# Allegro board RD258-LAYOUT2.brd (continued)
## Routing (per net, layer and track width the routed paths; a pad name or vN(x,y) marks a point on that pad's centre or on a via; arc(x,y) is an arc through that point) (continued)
SIG00089: length 1.9
  BOTTOM w0.15: R70.1 62.45,45.75 62.45,46.88 62.42,46.9 Q10.1
SIG00090: length 4.9
  BOTTOM w0.15: Q10.3 63.58,47.9 63.83,48.15 R67.1 65.25,48.8 C78.2 66.25,48.8 66.3,48.85 IC23.1
SIG00092: length 3.3
  BOTTOM w0.2: IC27.1 70.4,49.15 70.1,48.85 IC23.6
SIG00094: length 4.5
  BOTTOM w0.15: IC22.1 72,52.8 72.1,52.9 72.1,53.85 71.95,54 71.4,54 70.85,53.45 70.1,53.45 69.9,53.65 IC27.7
SIG00096: length 1.2
  BOTTOM w0.15: R72.1 72.53,54.62 IC22.4
SIG00097: length 5
  BOTTOM w0.3: R74.2 75.2,53.25 Q9.1 ; R74.2 R72.2 ; R74.2 TP39.1
SIG00098: length 1.2
  BOTTOM w0.15: IC26.6 73.4,38.75 Q8.1
SIG00099: length 4.7
  BOTTOM w0.15: IC31.3 20.8,32.15 20.9,32.25 20.9,32.95 R79.2 20.45,34.25 21,34.8 C87.2
SIG00100: length 3.4
  BOTTOM w0.2: R79.1 21.3,32.75 21.3,31.2 21.65,30.85 IC31.6
SIG00101: length 3.1
  BOTTOM w0.2: IC32.1 23.7,31.05 22.6,32.15 IC31.4
SIG00103: length 3.1
  BOTTOM w0.15: IC32.6 23.7,27.2 22.9,26.4 22.55,26.4 Q12.1
SIG00104: length 6.2
  BOTTOM w0.15: Q12.3 D25.1 20.7,21.25 R75.1 22.18,21 Q11.1
SIG00106: length 16.4
  BOTTOM w0.15: IC30.3 24.9,35.35 R83.2 25,34 C86.2 27.1,31.6 27.1,26.75 24.7,24.35 R78.1
SIG00107: length 2.6
  BOTTOM w0.15: IC30.1 R81.2 R76.1
SIG00108: length 11.4
  BOTTOM w0.15: R80.2 25.15,40.65 25.35,40.45 25.35,39.05 24.9,38.6 IC30.4
SIG00109: length 2.1
  BOTTOM w0.15: R80.1 16.25,37.08 Q14.1
SIG00110: length 6.4
  BOTTOM w0.15: Q14.3 14.4,35.98 14.4,34.2 R77.1 14.8,33.8 C88.2 15.1,32.15 IC28.1
SIG00112: length 2.5
  BOTTOM w0.15: IC28.6 17.43,32.15 16.88,31.6 16.7,31.6 16.6,31.5 IC33.1
SIG00114: length 3
  BOTTOM w0.15: IC29.1 IC33.7
SIG00115: length 1.2
  BOTTOM w0.15: R82.1 IC29.4
SIG00117: length 7.2
  TOP w0.3: v1(14.4,23.2) 14.4,24.45 TP40.1
  BOTTOM w0.3: v1(14.4,23.2) R82.2 R84.2 16.3,21.3 Q13.1
SIG00118: length 14.2
  TOP w0.15: v2(56.5,49.1) 54.8,49.1 53.85,48.15 53.85,45.77 54.35,45.27 59.88,45.27 v2(60.35,44.8)
  BOTTOM w0.15: v2(56.5,49.1) 56.35,48.68 IC36.4 ; IC34.6 v2(60.35,44.8)
SIG00119: length 15.4
  TOP w0.15: v2(55.2,44.7) 59.3,44.7 v2(60.35,43.65)
  BOTTOM w0.15: R98.1 61,44.3 v2(60.35,43.65) ; 55.35,46.95 IC36.6 ; 55.35,46.95 55.2,46.95 ; 55.35,46.95 55.2,46.8 ; 55.35,46.95 55.2,47.1 ; IC34.2 55.6,44.3 v2(55.2,44.7) 55.2,46.8 ; 55.2,46.8 55.2,46.95 ; 55.2,47.1 55.2,46.95 ; 55.2,47.1 55.2,48 54.95,48.25 IC36.3
SIG00120: length 3.5
  BOTTOM w0.15: IC37.1 59.7,48.65 C99.2 61,48.85 R98.2
SIG00121: length 10.6
  TOP w0.15: v2(59,46.1) 58.48,45.58 54.98,45.58 v2(54.45,46.1)
  BOTTOM w0.15: IC34.1 55.25,43.8 54.45,44.6 v2(54.45,46.1) ; v2(59,46.1) 58.15,46.95 IC37.4
SIG00122: length 9.3
  TOP w0.15: IC35.7 62.25,47.15 61.9,46.8 60.6,46.8 TP30.1 60.08,46.92 56.77,46.92 v2(55.95,46.1)
  BOTTOM w0.15: IC34.3 56.2,44.8 55.95,45.05 v2(55.95,46.1)
SIG00123: length 11
  TOP w0.15: v2(57.05,46.1) 57.58,46.62 59.27,46.62 60.15,45.75 61.6,45.75 TP32.1 62.75,46.9 IC35.8
  BOTTOM w0.15: v2(57.05,46.1) 57.9,46.1 58.5,45.5 58.5,44.6 58.8,44.3 IC34.7
SIG00124: length 4.7
  BOTTOM w0.15: IC37.6 58.25,48.25 58.5,48 58.5,47.4 58.95,46.95 IC37.3 59.7,45.44 59.56,45.3 IC34.5
SIG00126: length 8.2
  TOP w0.2: R90.1 67.8,52.35 63.55,52.35 62.25,51.05 IC35.4
SIG00127: length 4.2
  TOP w0.15: v2(64.5,51.65) 63.45,51.65 62.75,50.95 IC35.3
  BOTTOM w0.15: C94.2 63.42,51.15 63.92,51.65 v2(64.5,51.65)
SIG00129: length 7.8
  TOP w0.2: R103.1 68.8,48.45 67,46.65 64.4,46.65 63.75,47.3 IC35.10
SIG00130: length 1.7
  TOP w0.2: R103.2 71.7,49.85 Q16.3
SIG00132: length 4.1
  TOP w0.2: R90.2 73.65,51.35 73.8,51.5 Q15.3
SIG00134: length 1.2
  BOTTOM w0.15: Q17.3 R104.2
SIG00137: length 2.8
  TOP w0.5: R85.2 R86.1
SIG00138: length 3.2
  TOP w0.5: R86.2 D26.1
SIG00139: length 2.4
  TOP w1: D26.2 77.55,21.7 D27.1
SIG00140: length 2.4
  TOP w1: D28.1 82.35,22.7 D27.2
SIG00141: length 2.4
  TOP w1: D29.1 87.15,23.7 D28.2
SIG00142: length 13.3
  TOP w0.15: v2(38.7,23.35) 37.88,24.18 33.38,24.18 33.1,23.9 IC40.6 32.05,23.9 31.6,23.45 31.6,22.75 31.45,22.6 IC40.3 30.35,22.6 30.15,22.4 v2(30.15,21.8)
  BOTTOM w0.15: R119.1 v2(30.15,21.8) ; IC38.2 v2(38.7,23.35)
SIG00143: length 10.1
  TOP w0.15: v2(38.7,24.35) 39.4,23.65 39.4,23.1 39.05,22.75 38.2,22.75 37.35,23.6 v2(34,23.6)
  BOTTOM w0.15: v2(34,23.6) 33.7,23.9 IC41.4 ; v2(38.7,24.35) 38.2,23.85 IC38.1
SIG00144: length 6.3
  TOP w0.15: IC39.7 35.75,19.6 36.25,20.1 TP35.1 37.47,20.57 v2(37.85,20.8)
  BOTTOM w0.15: IC38.3 38.1,22.85 38.35,22.6 38.35,21.3 v2(37.85,20.8)
SIG00145: length 3.9
  BOTTOM w0.15: IC41.1 29.25,22.6 R119.2 C111.2
SIG00146: length 6.1
  TOP w0.15: IC39.8 35.25,19.3 34.8,19.75 TP37.1 35.1,20.1 v2(35.8,20.8)
  BOTTOM w0.15: IC38.7 35.5,23.35 35.8,23.05 v2(35.8,20.8)
SIG00147: length 2.3
  TOP w0.15: v2(34,22.6) IC40.4
  BOTTOM w0.15: IC38.6 34.25,22.85 v2(34,22.6)
SIG00148: length 5.3
  BOTTOM w0.15: IC41.3 31.35,23.9 31.6,23.65 31.6,23.1 32.1,22.6 IC41.6 33.2,22.6 33.75,22.05 34.45,22.05 34.75,22.35 IC38.5
SIG00150: length 8.5
  TOP w0.2: R110.1 29.2,14.3 29.55,13.95 34.45,13.95 35.75,15.25 IC39.4
SIG00151: length 4.6
  TOP w0.15: v2(33.05,14.5) 34.4,14.5 35.25,15.35 IC39.3
  BOTTOM w0.15: C106.2 32.17,13.62 v2(33.05,14.5)
SIG00153: length 4
  TOP w0.2: Q18.3 24.2,14.75 24.4,14.95 R110.2
SIG00155: length 7.6
  TOP w0.2: R123.1 29.2,17.75 31.1,19.65 33.5,19.65 34.25,18.9 IC39.10
SIG00156: length 1.7
  TOP w0.2: Q19.3 26.3,16.45 R123.2
SIG00158: length 1.4
  BOTTOM w0.15: Q20.3 R124.2
SIG00161: length 2.8
  TOP w0.5: R106.1 R105.2
SIG00162: length 3.6
  TOP w0.5: R106.2 28.55,63.5 D34.1
SIG00163: length 2.2
  TOP w1: D35.1 D34.2
SIG00164: length 2.2
  TOP w1: D36.1 D35.2
SIG00165: length 2.2
  TOP w1: D37.1 D36.2
SIG00167: length 11.2
  BOTTOM w0.15: R178.2 R128.1 57.95,15.82 58.17,15.6 63.7,15.6 66.08,13.22 Q22.1
SIG00168: length 2.4
  BOTTOM w0.15: R133.2 R131.1
SIG00169: length 1.7
  BOTTOM w0.15: R136.1 57.2,19.25 Q24.1
SIG00170: length 10.1
  TOP w0.15: R129.1 58.73,13.25 C120.2 58.88,13.25 R132.2 61,12.4 64.4,12.4 v2(64.85,11.95)
  BOTTOM w0.15: IC51.3 65.08,11.35 65.06,11.39 v2(64.85,11.95)
SIG00171: length 3
  BOTTOM w0.15: 70.45,4.28 R126.1 R179.2
SIG00173: length 3.1
  BOTTOM w0.15: Q23.3 68.47,5.42 R135.2 68.3,5.35 67.95,5 D42.2
SIG00174: length 2.4
  BOTTOM w0.15: Q25.1 71.2,8.7 R138.1
SIG00175: length 6.2
  BOTTOM w0.15: IC51.6 65.08,5.38 D42.1 64.85,4.4 R127.1 63.58,2.75
SIG00176: length 12.6
  TOP w0.15: v2(70.15,11.6) 68.8,10.25 64.45,10.25 v2(63.65,11.05)
  BOTTOM w0.15: v2(63.65,11.05) 63.77,10.46 IC51.1 ; R137.1 C128.2 70.15,10.7 v2(70.15,11.6) 70.75,12.2 IC48.1
SIG00177: length 2.8
  TOP w0.15: R143.2 64.85,5.75 v2(64.42,5.9)
  BOTTOM w0.15: IC51.7 v2(64.42,5.9)
SIG00178: length 19.6
  TOP w0.15: R143.1 R139.1 69.65,4.7 C129.2 71.6,4.7 73.35,6.45 73.35,8.9 71.4,10.85 71.4,11.9 70.55,12.75 v2(70.15,12.95)
  BOTTOM w0.15: v2(70.15,12.95) 70.3,13.25 70.3,14.5 71.4,15.6 IC42.1
SIG00179: length 1.3
  TOP w0.3: R142.2 R140.1
SIG00180: length 4.3
  TOP w0.3: 58.13,7.78 56.62,7.78 R147.2 55.23,7.85 C131.2 55.05,7.72 R142.1
SIG00181: length 6.2
  TOP w0.3: 62.47,7.78 61.12,7.78 60.48,7.12 IC50.4 58.13,5.98 R146.2
SIG00182: length 3.7
  TOP w0.3: R146.1 60.3,5.7 R149.2 61.73,7.12 IC50.5
SIG00183: length 14.7
  TOP w0.15: TP46.1 72.7,12.15 v2(74.6,14.05)
  BOTTOM w0.15: IC49.5 71.25,22.05 74.8,18.5 74.8,14.45 v2(74.6,14.05) 74.05,13.5 IC48.4
SIG00184: length 1.5
  TOP w0.15: R144.2 63.52,9.07 IC50.8
SIG00185: length 15.6
  TOP w0.15: v2(67.2,14.25) 67.95,13.5 68.7,13.5 69.95,12.25 70.35,12.25 70.8,11.8 70.8,9.65 C132.2 R144.1
  BOTTOM w0.15: IC45.1 67.6,14.65 v2(67.2,14.25)
SIG00186: length 14.9
  BOTTOM w0.15: IC53.1 62,31 62.1,31.1 62.1,32.3 61.85,32.55 60.3,32.55 58.9,31.15 58.9,24.4 58.2,23.7 57.45,23.7 57.15,24 IC47.3
SIG00190: length 25.8
  TOP w0.15: v2(70.88,21.12) 70.88,23.57 v2(71.2,23.9)
  BOTTOM w0.15: v2(70.88,21.12) 70.88,19.88 71.4,19.35 IC42.6 71.4,18.15 70.9,17.65 70.35,17.65 70.1,17.4 IC42.3 ; R138.2 73.35,10.65 75.4,12.7 75.4,19.7 v2(71.2,23.9)
SIG00191: length 12.3
  TOP w0.15: v2(66.9,25.9) v2(64.85,25.9)
  BOTTOM w0.15: IC46.1 v2(64.85,25.9) ; IC42.4 69.85,18.8 69.17,19.48 69.17,20.16 68.8,20.53 68.42,20.53 67.3,21.65 67.3,25.5 v2(66.9,25.9)
SIG00192: length 2.9
  BOTTOM w0.15: IC45.3 66.3,17.55 66.4,17.65 67.15,17.65 67.6,18.1 IC45.6
SIG00193: length 2.8
  BOTTOM w0.15: IC48.6 72.75,12.2 72.3,12.65 72.3,13.3 72.1,13.5 IC48.3
SIG00194: length 19.3
  TOP w0.15: v2(65.4,28) v2(66.9,28)
  BOTTOM w0.15: IC45.4 66.3,19.95 66.9,20.55 66.9,25 66.35,25.55 66.35,27.45 v2(66.9,28) 67.85,27.05 68.95,27.05 69.75,26.25 IC49.1 ; IC46.2 65.4,24.5 v2(65.4,28)
SIG00195: length 1.9
  BOTTOM w0.15: IC43.2 61.55,25.1 61.65,25.2 61.95,25.2 62.05,25.1 IC43.3
SIG00196: length 13.4
  TOP w0.15: v2(62.35,20.8) 61.9,20.35 61.35,20.35 61.1,20.1 61.1,19.4 60.75,19.05 59.9,19.05 59.3,19.65 57.2,19.65 TP45.1
  BOTTOM w0.15: v2(62.35,20.8) 62.55,21.2 IC43.5 62.55,22.3 62.65,22.4 62.96,22.4 63.05,22.31 63.05,21.37 63.44,20.98 65.03,20.98 65.35,21.3 IC46.7
SIG00197: length 1.9
  BOTTOM w0.15: IC49.2 70.25,26.15 70.4,26.3 70.6,26.3 70.75,26.15 IC49.3
SIG00198: length 6.2
  BOTTOM w0.15: IC46.5 66.35,20.95 65.78,20.38 63.17,20.38 62.15,19.35 IC44.4
SIG00199: length 11.4
  BOTTOM w0.15: IC43.7 61.55,22.4 61.7,22.55 61.95,22.55 62.05,22.45 IC43.6 62.05,21.3 61.42,20.68 59.83,20.68 59.35,21.15 59.35,21.7 59,22.05 58.25,22.05 57.95,21.75 IC47.5 57.65,22.55 56.15,24.05 IC47.1
SIG00200: length 4.1
  BOTTOM w0.15: R130.1 R134.2 66.95,6.1 66.05,6.1 65.72,6.42 IC51.5
SIG00203: length 4.6
  BOTTOM w0.15: R151.1 34.25,63.45 R183.2 32.55,63.45 31.3,62.2 Q28.1
SIG00204: length 4.7
  TOP w0.15: R158.2 31.15,58.8 31.15,59.35 R156.1
SIG00205: length 2.8
  BOTTOM w0.15: R161.1 36.85,61.95 37.15,62.25 37.55,62.25 38.3,63 Q30.1
SIG00206: length 8.1
  BOTTOM w0.15: 36.92,60.3 36.35,59.73 36.35,58.9 36.7,58.55 R157.2 36.2,58 35.35,58.85 R154.1 35.1,59.6 33.35,59.6 33.02,59.27 33.02,58.6
SIG00208: length 3.6
  BOTTOM w0.15: Q29.1 38.65,49.95 38.55,49.85 37.75,49.85 R152.1 R184.2
SIG00209: length 5.8
  BOTTOM w0.15: Q29.3 38.45,51.77 38.45,53.05 38.2,53.3 36.85,53.3 R160.2 35.55,52.65 D43.2
SIG00210: length 5.1
  BOTTOM w0.15: 33.02,56 33.02,54.75 33.5,54.27 33.5,54.08 34.42,54.08 D43.1 35.9,53.65 R153.1
SIG00211: length 1.5
  BOTTOM w0.15: R150.1 36.55,56.55 R155.2
SIG00212: length 3
  BOTTOM w0.15: R159.2 35.05,56.25 R155.1 34.05,55.25 33.67,55.62 IC64.5
SIG00213: length 1.3
  BOTTOM w0.15: Q31.1 R163.1
SIG00215: length 10.9
  BOTTOM w0.15: IC54.1 25.75,53.3 26.55,54.1 28.5,54.1 C147.2 29.95,52.65 R164.1 R168.1
SIG00216: length 6.2
  TOP w0.3: IC62.3 34.98,51.73 35.3,51.4 35.3,51.1 36.17,50.23 C151.2 38.12,50.23 R172.2 R167.1
SIG00217: length 1.2
  TOP w0.3: R165.1 R167.2
SIG00218: length 6.7
  TOP w0.3: R171.2 34,53.8 34.27,53.53 IC62.4 32.23,52.38 31.57,51.73 IC62.6
SIG00219: length 4.4
  TOP w0.3: IC62.5 31.43,52.38 31.9,52.85 R171.1 R173.2
SIG00220: length 13
  BOTTOM w0.15: 29.65,40.6 29.65,40.7 ; 29.65,40.6 29.75,40.7 ; 29.65,40.6 29.55,40.7 ; 29.65,40.6 IC55.7 ; 29.65,40.7 29.75,40.7 ; 29.65,40.7 29.55,40.7 ; IC59.1 34.65,43.05 33.15,44.55 IC59.5 32.4,45.15 32.1,44.85 32.1,41.35 31.45,40.7 29.75,40.7 ; IC55.6 29.15,40.6 29.25,40.7 29.55,40.7
SIG00221: length 2.2
  TOP w0.15: R169.2 31.15,49.92 30.65,50.42 IC62.8
SIG00222: length 7.3
  TOP w0.15: C152.2 32.7,47.7 R169.1 31.15,46.45 31.9,45.7 31.9,44.15 32.35,43.7 IC57.1
SIG00223: length 11.2
  TOP w0.15: IC65.1 31,38.4 31.1,38.5 32.3,38.5 v2(33.55,37.25)
  BOTTOM w0.15: IC59.3 33.65,43.01 33.51,43.15 32.84,43.15 32.7,43.01 32.7,41 33.55,40.15 v2(33.55,37.25)
SIG00227: length 25.1
  TOP w0.15: v2(38.7,43.3) 36.7,43.3 34.1,40.7 30.2,40.7 29.7,41.2 29.7,46.99 29.29,47.4 27.2,47.4 v2(26.65,46.85)
  BOTTOM w0.15: IC54.3 27.05,49.19 26.91,49.05 26.25,49.05 25.75,48.55 IC54.6 25.75,47.2 26.1,46.85 v2(26.65,46.85) ; R163.2 38.7,44.25 v2(38.7,43.3)
SIG00228: length 6.7
  BOTTOM w0.15: IC58.1 31,47.5 31.2,47.3 31.2,46.8 30.68,46.27 27.77,46.27 27.18,46.88 27.18,47.73 IC54.4
SIG00229: length 2.8
  TOP w0.15: IC57.6 34.2,43.7 34.02,43.52 34.02,42.88 33.55,42.4 IC57.3
SIG00230: length 2.7
  BOTTOM w0.15: IC60.6 27.35,44.25 26.7,43.6 26.3,43.6 26.05,43.35 IC60.3
SIG00231: length 12.5
  TOP w0.15: IC57.4 34,42.4 32.9,41.3 30.74,41.3 v2(30.3,41.4) 30.3,46.5 v2(30.5,46.9)
  BOTTOM w0.15: IC61.1 30.2,41.84 v2(30.3,41.4) ; IC58.2 v2(30.5,46.9)
SIG00232: length 1.8
  BOTTOM w0.15: IC61.2 29.7,41.85 29.6,41.75 29.3,41.75 29.2,41.85 IC61.3
SIG00233: length 1.4
  BOTTOM w0.15: IC55.2 29.65,37.61 29.51,37.75 29.29,37.75 29.15,37.61 IC55.3
SIG00234: length 22
  TOP w0.15: v2(22.8,45.85) 23.5,45.85 TP47.1 27.05,47.7 29.15,47.7 30.1,48.65 v2(30.1,49.35)
  BOTTOM w0.15: IC58.7 30.5,49.75 v2(30.1,49.35) ; IC55.5 28.65,40.66 28.28,41.02 24.32,41.02 22.8,42.55 v2(22.8,45.85)
SIG00235: length 5.9
  TOP w0.15: TP48.1 v2(26.3,45.85)
  BOTTOM w0.15: IC60.4 26.05,45.6 v2(26.3,45.85) 28.55,45.85 28.7,45.7 IC61.5
SIG00236: length 5.6
  BOTTOM w0.15: IC58.5 29.5,51.35 29.9,51.75 32,51.75 33.45,50.3 IC56.4
SIG00238: length 5.6
  TOP w1: P2.1 90.95,30.2 D29.2
SIG00239: length 6.5
  TOP w1: D37.2 9.1,58.6 P5.1
STO_VMOS_A: length 77.9
  TOP w0.15: v2(54.3,16.65) 55.05,16.65 TP43.1 56.55,16.65 59.75,16.65 62.9,19.8 v2(63.45,19.8)
  BOTTOM w0.15: v2(54.3,16.65) 51.4,19.55 51.4,51.15 62.95,62.7 74.5,62.7 R104.1
  BOTTOM w0.2: IC44.6 v2(63.45,19.8)
STO_VMOS_B: length 68.6
  TOP w0.15: v2(33.5,47.1) v2(34.85,47.1) 35.38,46.58 37.42,46.58 TP44.1
  BOTTOM w0.15: v2(33.5,47.1) 32.85,47.75 32.85,48.9 33.4,49.45 34.6,49.45 34.75,49.6 IC56.6 ; R124.1 33.4,4.65 40.3,11.55 40.3,38 37.9,40.4 37.9,43.2 37.5,43.6 36.8,43.6 36.5,43.9 36.5,45.1 36.42,45.17 36.42,46.02 35.35,47.1 v2(34.85,47.1)
VE_A: length 105
  TOP w0.5: D30.1 67.6,19.6 ; D30.1 68.7,18.5 ; D30.1 66.5,18.5 ; CN2.3 54.3,31.46 ; CN2.3 56.38,31.46 ; CN2.3 55.23,32.61 ; D31.1 68.75,18.1 ; D31.1 69.7,19 ; D31.1 70.65,18.1 ; CN2.4 57.77,32.61 ; CN2.4 56.62,31.46 ; CN2.4 58.9,31.46 ; C89.1 65.33,17.5 ; C89.1 64.35,18.45 ; C89.1 63.38,17.5 ; 61.75,22.15 IC17.3 61.84,23.01 C47.2 64.6,23.01 ; 62.85,13.95 R87.1 62.1,13.15 ; R33.1 65.7,32.5 v1(65.95,33.05) ; C120.1 58.8,15.5 ; R132.1 60.15,15.45 ; IC17.1 59.85,22.3
  CONDUCTIVE2 w0.3: CN2.4 56.67,31.46 ; CN2.4 57.77,30.36 ; CN2.4 57.77,32.56 ; CN2.4 58.87,31.46 ; CN2.3 54.13,31.46 ; CN2.3 55.23,30.36 ; CN2.3 56.33,31.46 ; CN2.3 55.23,32.56
  BOTTOM w0.15: 53.95,22.4 53.95,21.7 54.63,21.02 55.73,21.02 v1(56.05,20.7)
  BOTTOM w0.3: v1(54.5,19.95) 52.75,21.7 52.75,40 v1(54.4,41.65) 52.75,43.3 52.75,50.4 v1(54.4,52.05) ; v1(68.35,12.75) 67.88,13.22 Q22.2 ; 69.65,4.28 69.65,4.25 69.25,3.85 R135.1 ; v1(54.4,43.5) 55.4,42.5 55.4,40.85 53.95,39.4 53.95,32.74 CN2.3 53.95,30.18 53.95,22.4
  BOTTOM w0.5: v1(60.75,2.6) 61.33,2.75 C121.1 ; R133.1 v1(59.25,4.3) ; R135.1 68.2,3.85 v1(67.4,3.9) ; R134.1 69.21,6.5 v1(70,6.4)
  BOTTOM w1: CN2.4 CN2.3
  vias: v1(54.65,65.55) v1(58.7,21.35) v1(59.45,65.55) v1(59.75,37.8) v1(59.8,36.3) v1(61.6,37.8) v1(61.6,36.3) v1(61.6,14.95) v1(61.75,13.15) v1(66.5,58.35) v1(66.5,56.85) v1(66.5,55.35) v1(66.5,53.85) v1(67.3,19.9) v1(67.7,63.95) v1(69.25,44.1) v1(69.25,43.1) v1(69.6,38.9) v1(69.6,37.7) v1(69.85,19.9) v1(71.95,65.55) v1(84.25,61.4) v1(84.25,60.4) v1(85.45,65.55) v1(89.45,65.55) v1(97.5,59.65) v1(97.5,54.65) v1(97.5,49.65)
VE_B: length 91.7
  TOP w0.15: 35.45,41.6 35.9,42.05 36.55,42.05 36.8,41.8 37.6,41.8 37.9,42.1 v1(38.6,42.1)
  TOP w0.3: 36.52,40.5 35.95,40.5 35.45,41 35.45,41.6 ; 39.35,29.31 39.35,27.6 39.05,27.3 37.4,27.3 v1(36.85,26.75) 36,25.9 32.25,25.9 31.65,25.3 v1(30.1,25.3) ; v1(33.8,24.8) 36.4,24.8 37.9,26.3 v1(38.6,26.3) 39.5,26.3 40.25,27.05 40.25,40.45 v1(38.6,42.1)
  TOP w0.5: CN3.3 34.08,31.46 ; CN3.3 36.38,31.46 ; CN3.3 35.23,32.61 ; CN3.4 37.77,32.61 ; CN3.4 36.62,31.46 ; CN3.4 39.15,31.46 ; 13.35,18.57 C104.2 14.2,19.4 ; 14.21,36.57 C66.2 15.3,36.81 IC21.3 v1(14,38.2) ; R54.1 27.89,32.5 v1(28.65,32.25) ; v1(37.1,59.17) 37.1,58.45 37.35,58.2 C101.1 ; v1(27.85,58.3) 27.9,57.7 R158.1 ; 16.25,40.1 IC21.1 v1(14,40.1) ; v1(34.85,65.6) 35.42,65.4 D39.1 36.25,65.3 D38.1
  CONDUCTIVE2 w0.3: CN3.4 37.77,32.56 ; CN3.4 36.67,31.46 ; CN3.4 37.77,30.36 ; CN3.4 38.87,31.46 ; CN3.3 35.23,32.56 ; CN3.3 34.13,31.46 ; CN3.3 36.33,31.46 ; CN3.3 35.23,30.36
  BOTTOM w0.3: C110.2 11.1,20.1 ; C110.2 11.82,20.85 ; C110.2 11.82,19.35 ; R160.1 37.3,52.25 v1(37.3,51.4) 37.3,50.98 Q29.2 ; Q28.2 32.77,61.48 R107.1
  BOTTOM w0.5: C141.1 33.5,52.05 v1(33.05,51.6) ; R159.1 34.55,57.85 v1(34.1,57.4) ; R157.1 38.2,58.8 ; CN3.4 37.77,30.31 ; CN3.4 36.62,31.46 ; CN3.4 37.77,32.61 ; CN3.3 35.23,30.31 ; CN3.3 35.23,32.61 ; CN3.3 34.08,31.46 ; CN3.3 36.38,31.46 ; v1(34.25,61.9) 33.66,62 R107.1 ; C140.1 38.27,59.45
  vias: v1(2.55,37.9) v1(2.55,32.9) v1(2.55,27.9) v1(2.55,22.9) v1(2.55,17.9) v1(2.55,12.9) v1(2.55,7.9) v1(8.7,20.1) v1(10,20.1) v1(10.75,32.85) v1(13.2,8.95) v1(13.2,7.45) v1(14,3.9) v1(14,2.4) v1(19.2,26.75) v1(19.2,25.35) v1(19.2,23.65) v1(25.75,23.5) v1(27.85,23.5) v1(28.65,33.4) v1(28.75,2.45) v1(29.75,27.4) v1(30.6,11.65) v1(30.6,10.3) v1(30.6,7.75)
VGATE_A: length 22.7
  TOP w0.2: IC35.5 v1(61.75,52)
  TOP w0.8: v1(74.05,59.9) v1(74.05,61.1) 66.55,61.1 63.15,57.7 63.15,54.6 61.75,53.2 v1(61.75,52)
  BOTTOM w0.5: C94.1 62.08,51.73 v1(61.75,52)
  vias: v1(81.05,52.3) v1(81.05,51.3) v1(82.05,52.3) v1(82.05,51.3)
VGATE_B: length 16.9
  TOP w0.2: v1(33.05,12.9) 34.3,12.9 36.25,14.85 IC39.5
  BOTTOM w0.5: v1(33.05,12.9) 32.42,12.28 31.32,12.28 30.95,12.65 24.3,12.65 22.4,14.55
  vias: v1(16.35,15) v1(16.35,14) v1(17.35,15) v1(17.35,14)
VGD_A: length 10.7
  TOP w0.5: v1(58.75,55.1) 58.75,54.1 57.8,53.15 R31.2
  BOTTOM w0.8: 62.7,55.2 v1(66.25,51.65) v1(67.25,51.65)
  BOTTOM w1: 61.3,55.2 62.7,55.2
  vias: v1(58.75,56.1)
VGD_B: length 1.2
  TOP w0.5: R52.2 35.65,11.45 v1(35.4,12)
  vias: v1(30.35,14.65) v1(31.35,14.65) v1(34.4,12)
VL_A: length 166
  TOP w0.3: R140.2 v1(55.05,4.15)
  TOP w0.4: R139.2 64.95,7.25 63.77,8.43 IC50.7 61.62,8.43 60.98,9.07 60.98,10.7
  TOP w0.5: 60.98,11.7 61.12,11.85 63.9,11.85 64.65,11.1 v1(66.3,11.1) ; C48.2 57.7,25.89 ; C48.2 56.79,25.04 ; C48.2 58.61,25.04 ; IC17.5 59,25.5
  TOP w0.6: 60.98,10.7 60.98,11.7
  TOP w0.8: 72.2,26.3 72.2,25.5 ; 72.2,26.3 v1(72.2,28.9) 73.75,30.45 73.75,36.85 v1(71.2,39.4) ; 72.2,26.3 71.4,25.5 ; 72.2,25.5 71.4,25.5 ; 72.2,25.5 72.2,24.7 ; 72.2,24.7 71.4,25.5 ; 72.2,24.7 72.2,23.05 71.75,22.6 v1(71.75,20.1) ; 71.4,25.5 70.65,25.5 68.8,23.65 v1(68.8,22.5) ; 60.98,11.7 60.55,11.7 59.95,12.3 55.5,12.3 v1(54.4,11.2) ; v1(56.95,50.9) 57.35,50.9 61.75,55.3 61.75,58.3 v1(63.1,59.65)
  CONDUCTIVE3 w1: 54,35.31 CN2.7 54.2,37.57
  BOTTOM w0.2: C72.2 72.97,52.35 IC22.5 ; 63.73,40.15 64.15,40.58 64.15,42.45 63.85,42.75 IC24.5 ; C124.1 62.52,29.93 IC53.5 ; C70.2 68.9,47.83 68.9,49.35 69.05,49.5 IC23.5 ; IC44.5 62.8,18.25 62.65,18.1 61.38,18.1 60.9,18.57 C115.1 ; IC7.5 61.17,28.25 C24.1 ; C69.2 70.8,38.23 71.03,38 72.61,38 72.7,38.09 IC26.5
  BOTTOM w0.25: C100.2 57.08,48.9 57.08,47.77 57.25,47.6 IC37.5
  BOTTOM w0.3: 73.78,15 72.7,13.93 72.7,13.15 73,12.85 IC48.5 ; IC34.8 59.08,43.8 58.88,43.6 C93.2 ; v1(66.3,11.1) 66.8,10.6 R137.2 ; C118.2 55.33,23.1 56.15,22.27 IC47.8 ; IC43.8 61.05,22.23 60.85,22.43 C113.2 59.9,21.9 v1(60.15,21.35) ; IC49.8 69.75,23.35 69.42,23.68 C123.2 68.6,23.07 v1(68.8,22.5) ; C124.1 61.3,28.35 C24.1 ; C96.2 55.6,49.77 55.6,47.85 55.85,47.6 IC36.5 ; v1(63.7,21.9) C117.2 64.33,23.12 64.85,22.6 IC46.8 ; IC27.8 70.4,55.48 C73.2 ; IC45.5 66.95,18.2 66.78,18.02 65.55,18.02 C119.1 ; IC42.5 70.75,18.3 70.47,18.02 69.4,18.02 C114.1 ; IC25.5 70.6,32.25 70.85,32 70.85,30.98 C76.2
  BOTTOM w0.5: C96.2 v1(56.95,50.9) 57.73,50.12 C100.2 ; C72.2 72.97,50.33 C71.2 73.05,48.99 ; 69.33,46.55 C70.2 70.15,47.4 ; v1(60.4,19.75) 60.4,19.07 60.75,18.73 C115.1 ; v1(63.1,59.65) 67.42,59.65 70.33,56.75 C73.2 ; C114.1 68.55,18.88 v1(68.55,19.9) ; v1(54.95,21.8) C118.2 ; v1(71.2,39.4) 70.75,38.95 C69.2 ; 73.78,15 73.78,18.07 v1(71.75,20.1) ; v1(59.85,26.65) 59.85,27.85 60.35,28.35 C24.1 ; v1(72.2,28.9) 70.65,28.9 70.08,29.48 C76.2 ; C119.1 65,19.15 v1(65.6,19.75) ; R67.2 65.4,45.85 R66.2 v1(66.45,45.35) ; 63.73,40.15 v1(61.05,40.15) ; C93.2 v1(60.15,42.55)
  vias: v1(56.7,26.35) v1(58.1,26.35) v1(67.45,45.35)
VL_B: length 133.5
  TOP w0.2: IC65.5 29.73,38.92 C144.1
  TOP w0.3: 29.93,51.08 28.65,51.08 28.6,51.02 ; C108.2 32,21.82 32,23.05 32.2,23.25 IC40.5 ; IC57.5 35.3,43.05 35.5,43.25 35.5,44.33 C139.1 ; v1(36,51.4) 36,52.3 R165.2
  TOP w0.5: C108.2 32.83,21 v1(33.75,21) ; v1(28.9,35.5) v1(32.9,35.5) ; v1(28.25,48.35) 28.25,50.67 28.6,51.02 ; C67.2 v1(20.65,39.94) ; C67.2 17.86,39.94 IC21.5 ; C67.2 TP19.1 ; C139.1 35.27,45.45 v1(35.8,45.45) ; v1(27.5,40) 28.7,38.8 C144.1
  TOP w0.8: CN3.7 34.19,35.5 v1(32.9,35.5) ; v1(35.42,26.75) v1(32.75,26.75)
  CONDUCTIVE3 w1: 35.23,37.6 CN3.7 34.3,36.54 ; 15.9,27.8 15.9,32.6 ; 16.85,33.88 16.85,37.74 19.05,39.94 v1(20.65,39.94) 20.65,40.13 24.75,44.23 v1(24.75,45.65) ; v1(30.8,55.2) 29.65,54.05 27.55,54.05 25.2,51.7 25.2,51.08
  BOTTOM w0.2: IC60.5 26.7,44.2 26.55,44.05 25.18,44.05 24.75,44.48 ; IC29.5 15.55,24.43 ; 31.7,35.48 31.45,35.23 IC11.5
  BOTTOM w0.3: IC38.8 35.23,23.85 35.42,24.05 35.42,25.1 ; 28.3,49.42 28.02,49.42 27.25,48.65 26.7,48.65 26.4,48.35 IC54.5 ; 31.4,44.58 31.32,44.65 30.5,44.65 30.2,44.95 IC61.8 ; 31.4,44.58 31.4,44.48 ; 31.4,44.58 31.4,44.87 v1(31.25,45.45) ; IC55.8 30.15,39.42 30.35,39.23 C133.2 ; IC31.5 22.55,31.5 22.8,31.25 22.8,30.1 22.3,29.6 C85.2 ; C136.1 35.23,50.95 34.35,50.95 34.1,50.7 IC56.5 ; C81.2 15.55,27.23 C82.2 15.62,27.5 16.25,27.5 16.6,27.85 IC33.8 ; C81.2 15.55,24.43 C83.2 ; C81.2 16.5,25.7 ; IC40.5 32.23,23.25 32,23.48 32,24.77 C112.2 ; v1(35.8,45.45) 35.8,44.48 34.9,44.48 34.65,44.73 IC59.8 ; 25.5,28.93 C79.2 26.25,28.13 ; IC58.8 31,50.08 31.15,49.92 C137.2 32.15,50.65 v1(31.8,51) ; IC32.5 24.35,27.3 ; v1(20.65,39.94) 19.3,38.59 19.3,35.2 18.8,34.7 C80.2 17.45,34.33 17.45,33.05 17.7,32.8 IC28.5 ; C84.2 26.48,38.83 26.2,38.55 IC30.5
  BOTTOM w0.5: R162.2 28.6,55.05 30.22,55.05 v1(30.8,55.2) 30.9,54.61 R164.2 ; v1(28.9,35.5) 28.9,35.1 R76.2 ; C136.1 v1(36,51.4) ; R77.2 13.2,36 v1(12.35,36.85) ; C133.2 32.09,39.23 v1(32.62,39.5) ; 35.42,25.1 v1(35.42,26.75) ; 28.3,49.42 28.3,48.95 v1(28.25,48.35) ; C84.2 v1(27.5,40) ; 31.7,35.48 31.73,35.5 v1(32.9,35.5) ; v1(32.75,26.75) 32.48,26.22 C112.2 ; C85.2 v1(21.57,27.1) ; 24.75,44.48 v1(24.75,45.65)
  vias: v1(16.45,26.75)
N03856: length 8.8
  TOP w0.5: CN2.2 58.92,28.92 ; CN2.2 CN2.1 ; CN2.2 57.77,27.9 ; CN2.2 57.77,30.07 ; CN2.1 55.23,30 ; CN2.1 55.23,28 ; CN2.1 54.3,28.92
N03958: length 1.3
  TOP w0.5: R28.2 R27.1
N502328: length 5.8
  TOP w0.5: CN3.1 35.23,30.07 ; CN3.1 34.08,28.92 ; CN3.1 36.38,28.92 ; 37.77,30.07 CN3.2 36.62,28.92
N505177: length 1.3
  TOP w0.5: R49.2 R48.1
N855499: length 8.4
  BOTTOM w0.15: IC47.2 56.65,24.05 57.3,23.4 58.35,23.4 59.4,24.45 59.4,25.15 60.3,26.05 IC7.4 61.17,25.38 61.05,25.25 IC43.1
N855623: length 9.2
  BOTTOM w0.15: 59.05,13.45 59.05,13.1 58.8,12.85 56.83,12.85 C116.1 56.67,12.1 58.2,12.1 R131.2 ; 59.05,13.45 Q21.5 ; 59.05,13.45 59.05,13.95 58.9,14.1 Q21.2
N855675: length 1.5
  BOTTOM w0.15: R125.1 R130.2
N871149: length 14.9
  BOTTOM w0.15: 29.85,36.17 29.85,36.33 ; 29.85,36.17 30,36.17 ; 29.85,36.17 29.85,36.02 ; 29.85,36.33 30,36.17 ; 29.85,36.33 29.85,36.45 30.15,36.75 IC55.1 ; 30,36.17 31.46,36.17 33.25,37.97 33.25,39.95 32.4,40.8 32.4,43.21 32.64,43.45 33.75,43.45 34.15,43.05 IC59.2 ; 30,36.17 29.85,36.02 ; 29.85,36.02 IC11.4
N871259: length 7.4
  TOP w0.15: R156.2 32.5,59.05 33.17,58.38 C135.1 34.8,56.45 35.05,56.2 Q27.5 35.05,55.25 35.7,54.6 Q27.2
N872651: length 30.1
  BOTTOM w0.15: IC64.1 31.73,59.17 30.3,60.6 28.55,60.6 28.2,60.25 C149.2 28.55,59.2 28.55,57.8 R162.1 24.05,53.3 24.05,41.75 24.48,41.33 26.88,41.33 27.35,41.8 IC60.1
N1967382: length 1.5
  BOTTOM w0.15: Q21.3 57.1,14.75 R175.1
N1967396: length 1.5
  BOTTOM w0.15: R176.1 57.1,13.45 Q21.1
N1967438: length 3.9
  BOTTOM w0.3: Q21.4 60.5,14.75 61.05,14.2 R177.2
N1968040: length 1.4
  BOTTOM w0.15: Q25.3 71.7,4.45 R179.1
N1968066: length 2.7
  BOTTOM w0.15: R178.1 55.35,18.15 Q24.3
N1971632: length 2.1
  TOP w0.15: R180.1 37.05,54.85 36.6,54.85 36.35,54.6 Q27.3
N1971644: length 2.5
  TOP w0.15: R181.1 34.55,55.1 35.05,54.6 Q27.1
N1971690: length 3.5
  TOP w0.3: R182.2 35.2,57.3 36.35,56.15 Q27.4
N1972235: length 1.8
  BOTTOM w0.15: R184.1 38.6,47.7 38.5,47.6 Q31.3
N1972365: length 4.5
  BOTTOM w0.15: R183.1 Q30.3
N1974780: length 2
  BOTTOM w0.15: IC64.7 32.38,54.23 32.3,54.15 R168.2

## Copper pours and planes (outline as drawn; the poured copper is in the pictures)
VCC20_A on TOP: 71.06,51.65 71,51.66 70.96,51.69 70.22,52.43 70.2,52.45 70.19,52.48 70.18,52.54 70.15,52.63 70.15,59.4 70.19,59.51 70.3,59.55 72.94,59.55 73,59.54 73.04,59.51 73.11,59.44 73.14,59.4 73.15,59.34 73.15,51.8 73.11,51.69 73,51.65
VCC20_A on TOP: 69.2,30 69.13,30.03 69.1,30.1 69.1,30.95 69.06,31.06 68.95,31.1 68.14,31.1 68.07,31.13 68.04,31.2 68.04,34.3 68.08,34.41 68.19,34.45 72.65,34.45 72.72,34.42 72.75,34.35 72.75,30.48 72.74,30.44 72.72,30.41 72.34,30.03 72.31,30.01 72.27,30
VCC20_A on BOTTOM: 85.25,55.2 85.14,55.24 85.1,55.35 85.1,61.65 85.14,61.76 85.25,61.8 86.65,61.8 86.76,61.76 86.8,61.65 86.8,55.35 86.76,55.24 86.65,55.2
VCC20_A on CONDUCTIVE3: outline of 164 points within 53.91,2 87.1,61.8 ; 6 cut-outs
VCC20_B on TOP: 29.81,3.65 29.71,3.69 28.9,4.5 20.61,4.5 20.53,4.54 20.42,5.26 19.85,5.55 18.85,5.55 18.28,5.26 18.17,4.54 18.09,4.5 16.51,4.5 15,4.5 14.93,4.53 14.9,4.6 14.9,6.45 14.94,6.56 15.05,6.6 24.34,6.6 24.4,6.61 24.44,6.64 24.81,7.01 24.84,7.05 24.85,7.11 24.85,14.5 24.89,14.61 25,14.65 26.94,14.65 27.04,14.61 27.82,13.83 27.84,13.8 27.85,13.76 27.85,7.54 27.87,7.52 27.89,7.51 30.56,4.84 30.66,4.8 34.1,4.8 34.21,4.76 34.25,4.65 34.25,3.8 34.21,3.69 34.1,3.65
VCC20_B on TOP: 21.8,40 21.69,40.04 21.65,40.15 21.65,41.04 21.61,41.14 20.88,41.87 20.86,41.9 20.85,41.94 20.85,44.31 20.86,44.35 20.88,44.38 21.37,44.87 21.4,44.89 21.44,44.9 22.2,44.9 22.31,44.86 22.35,44.75 22.35,42.31 22.39,42.21 23.11,41.49 23.15,41.39 23.15,40.15 23.11,40.04 23,40
VCC20_B on TOP: 18.75,29.8 18.68,29.83 18.65,29.9 18.65,32.34 18.69,32.44 20.31,34.06 20.36,34.1 20.41,34.16 21.43,35.18 21.52,35.31 21.55,35.47 21.55,38.7 21.59,38.81 21.7,38.85 23,38.85 23.11,38.81 23.15,38.7 23.15,38.21 23.19,38.11 23.89,37.41 23.93,37.31 23.93,32.35 23.93,29.95 23.89,29.84 23.78,29.8
VCC20_B on BOTTOM: 15.2,4.25 15.13,4.28 15.1,4.35 15.1,7.29 15.06,7.39 14.53,7.92 14.51,7.95 14.5,7.99 14.5,9.3 14.54,9.41 14.65,9.45 15.66,9.45 15.7,9.44 15.73,9.42 17.06,8.09 17.1,7.99 17.1,4.4 17.06,4.29 16.95,4.25
VCC20_B on CONDUCTIVE3: outline of 167 points within 3.75,4.15 38.95,62.4 ; 5 cut-outs
VEE_A on TOP: 57.25,22.35 57.17,22.37 57.11,22.44 57.1,22.48 57.11,22.52 57.15,22.68 57.13,22.83 57.15,22.92 57.23,22.96 58.16,22.96 58.3,23.02 58.36,23.16 58.36,24.25 58.39,24.32 58.46,24.35 59.28,24.35 59.52,24.43 59.67,24.63 59.7,24.68 59.76,24.7 60.2,24.7 60.32,24.72 60.45,24.79 60.48,24.8 62.15,24.8 62.29,24.86 62.35,25 62.35,26.35 62.39,26.46 62.5,26.5 64.25,26.5 64.36,26.46 64.4,26.35 64.4,24.3 64.37,24.18 64.27,24.08 64.15,24.05 64.06,24.05 63.96,24.09 63.91,24.2 63.91,24.89 63.85,25.03 63.71,25.09 62.79,25.09 62.65,25.03 62.59,24.89 62.59,23.95 62.54,23.84 62.44,23.8 59.45,23.8 59.31,23.74 59.25,23.6 59.25,22.5 59.21,22.39 59.1,22.35
VEE_A on TOP: 65.41,46.95 65.31,46.99 65.01,47.29 64.98,47.33 64.94,47.36 64.19,48.11 64.15,48.14 64.09,48.15 59.54,48.15 59.5,48.16 59.47,48.18 59.33,48.32 59.31,48.35 59.3,48.39 59.3,49.04 59.26,49.14 58.94,49.46 58.9,49.56 58.9,50.84 58.94,50.94 59.12,51.12 59.15,51.14 59.19,51.15 59.94,51.15 60.04,51.11 61.36,49.79 61.46,49.75 65.05,49.75 65.16,49.71 65.2,49.6 65.2,49.05 65.31,48.94 65.41,48.9 66.9,48.9 67.01,48.86 67.05,48.75 67.05,47.09 67.04,47.06 67.02,47.02 66.98,46.98 66.94,46.96 66.91,46.95
VEE_A on BOTTOM: 68.15,13.73 68.06,13.74 67.98,13.8 67.85,13.92 67.83,13.95 67.83,13.99 67.83,16.23 67.84,16.28 67.97,16.39 68,16.5 68,16.55 68.03,16.62 68.1,16.65 69.56,16.65 69.63,16.63 69.69,16.58 69.7,16.55 69.7,16.5 69.76,16.36 69.9,16.3 70.8,16.3 70.87,16.27 70.9,16.2 70.9,15.46 70.89,15.42 70.87,15.39 70.14,14.66 70.09,14.59 70.08,14.5 70.08,13.83 70.05,13.76 69.98,13.73 69.97,13.73
VEE_A on BOTTOM: 54.6,24.15 54.53,24.18 54.5,24.25 54.5,27.2 54.54,27.31 54.65,27.35 55.25,27.35 55.36,27.31 55.4,27.2 55.4,26.31 55.41,26.25 55.44,26.21 55.96,25.69 56.06,25.65 58.38,25.65 58.48,25.61 58.52,25.5 58.52,24.4 58.52,24.37 58.51,24.34 58.43,24.26 58.4,24.25 58.37,24.25 58.1,24.25 58.03,24.28 58,24.35 58,24.8 57.94,24.94 57.8,25 56,25 55.86,24.94 55.8,24.8 55.8,24.3 55.76,24.19 55.65,24.15
VEE_A on BOTTOM: 69.55,56.23 69.51,56.15 69.42,56.14 69.38,56.15 69.35,56.15 68.6,56.15 68.46,56.09 68.4,55.95 68.4,55.15 68.43,55.05 68.5,54.98 68.52,54.96 68.54,54.93 68.55,54.89 68.55,53.85 68.61,53.71 68.75,53.65 69.45,53.65 69.52,53.62 69.55,53.55 69.55,52.2 69.51,52.09 69.4,52.05 68.75,52.05 68.61,51.99 68.55,51.85 68.55,51.4 68.53,51.33 68.48,51.28 68.46,51.26 68.43,51.26 68,51.26 67.91,51.3 67.83,52.04 67.25,52.35 66.59,52.35 66.54,52.36 66.51,52.39 66.08,52.95 66.04,52.99 63.88,55.15 63.86,55.18 63.85,55.22 63.85,57.36 63.86,57.4 63.88,57.43 64.21,57.76 64.26,57.79 64.31,57.8 66.45,57.8 66.5,57.8 66.55,57.8 68.45,57.8 68.49,57.79 68.52,57.77 69.52,56.78 69.54,56.74 69.55,56.71 ; 3 cut-outs
VEE_A on BOTTOM: 69.95,42.8 69.84,42.84 69.8,42.95 69.8,44.1 69.22,44.65 68.7,44.04 68.67,43.95 68.57,43.94 68.54,43.95 68.5,43.95 67.48,43.95 67.43,43.96 67.32,44.07 67.22,44.1 66.5,44.1 66.39,44.14 66.35,44.25 66.35,44.35 66.39,44.46 66.5,44.5 67.51,44.5 67.66,44.53 67.79,44.62 68.25,45.07 68.28,45.09 68.32,45.1 72,45.1 72.11,45.06 72.15,44.95 72.15,43.61 72.14,43.57 72.12,43.54 71.41,42.83 71.38,42.81 71.34,42.8
VEE_A on BOTTOM: 57.3,43.15 57.23,43.18 57.2,43.25 57.2,45.35 57.23,45.42 57.3,45.45 58.05,45.45 58.12,45.42 58.15,45.35 58.15,43.25 58.12,43.18 58.05,43.15
VEE_A on BOTTOM: 82.44,55.15 82.4,55.16 82.37,55.18 82.24,55.31 82.2,55.41 82.2,58.2 82.18,58.28 82.11,58.38 82.1,58.42 82.1,60.4 82.09,60.48 82.05,60.57 82.05,60.59 82.05,61.3 82.08,61.37 82.15,61.4 83.11,61.4 83.15,61.39 83.18,61.37 83.27,61.28 83.29,61.25 83.3,61.21 83.3,57.46 83.34,57.36 83.96,56.74 84,56.64 84,55.3 83.96,55.19 83.85,55.15
VEE_A on CONDUCTIVE3: outline of 213 points within 54.25,7.5 83.29,64.8 ; 37 cut-outs
VEE_B on TOP: 32.85,49.05 32.74,49.09 32.7,49.2 32.7,50.76 32.72,50.81 32.76,50.85 33.29,51.1 33.38,51.16 33.45,51.23 33.56,51.25 33.63,51.16 33.63,50.22 33.68,50.07 33.83,50.02 34.72,50.02 34.86,50.07 34.91,50.22 34.91,50.55 34.94,50.62 35.02,50.65 35.26,50.65 35.37,50.61 35.96,50.01 36.01,49.98 36.04,49.94 36.05,49.89 36.05,49.2 36.01,49.09 35.9,49.05
VEE_B on TOP: 17.14,37.04 17.08,37.18 16.94,37.24 16.14,37.24 16.1,37.23 16.03,37.26 16,37.33 16,39.25 16.04,39.36 16.15,39.4 16.85,39.4 16.96,39.36 17,39.25 17,37.8 17.06,37.66 17.2,37.6 18.2,37.6 18.33,37.65 18.43,37.84 18.5,37.86 19.76,37.86 19.9,37.92 19.96,38.06 19.96,38.8 19.99,38.87 20.06,38.9 21.1,38.9 21.21,38.86 21.25,38.75 21.25,35.47 21.24,35.43 21.22,35.4 20.19,34.37 20.1,34.27 18.48,32.66 18.38,32.51 18.35,32.34 18.35,22.35 18.31,22.24 18.2,22.2 15.49,22.2 15.4,22.18 15.31,22.13 15.12,21.9 15.1,21.79 15.1,21.65 15.07,21.58 15,21.55 12.05,21.55 11.94,21.59 11.9,21.7 11.9,24.85 11.91,24.89 12.65,26.12 12.9,27.5 12.65,28.88 11.91,30.11 11.9,30.15 11.9,34.25 11.91,34.31 11.94,34.35 13.47,35.88 13.5,35.9 13.54,35.91 16.94,35.91 17.08,35.97 17.14,36.11 ; 2 cut-outs
VEE_B on TOP: 26.29,18.45 26.25,18.46 26.22,18.48 25.83,18.87 25.81,18.9 25.8,18.94 25.8,21.95 25.83,22.02 25.9,22.05 27.75,22.05 27.82,22.02 27.85,21.95 27.85,18.79 27.88,18.7 27.95,18.64 28.02,18.53 27.92,18.45
VEE_B on TOP: 37.65,14.75 37.54,14.79 37.5,14.9 37.5,15.59 37.46,15.69 36.64,16.51 36.54,16.55 33.25,16.55 33.14,16.59 33.1,16.7 33.1,16.89 33.09,16.95 33.06,16.99 32.69,17.36 32.59,17.4 31.1,17.4 30.99,17.44 30.95,17.55 30.95,19.11 30.96,19.14 30.98,19.18 31.12,19.32 31.16,19.34 31.2,19.35 32.59,19.35 32.69,19.31 33.81,18.19 33.91,18.15 37.45,18.15 37.52,18.12 37.55,18.05 37.55,17.7 37.59,17.59 37.7,17.55 38.55,17.55 38.62,17.52 38.65,17.45 38.65,14.9 38.61,14.79 38.5,14.75
VEE_B on BOTTOM: 33.71,40.5 33.61,40.54 33.04,41.11 33,41.21 33,41.75 33.04,41.86 33.15,41.9 35.47,41.9 35.58,41.86 35.69,41.75 35.71,41.71 35.71,41.67 35.7,41.43 36.27,40.97 36.52,41.66 36.5,41.69 36.5,41.72 36.5,43.18 36.53,43.25 36.6,43.28 37.4,43.28 37.51,43.24 37.55,43.13 37.55,40.65 37.51,40.54 37.4,40.5
VEE_B on BOTTOM: 22.68,34.48 22.57,34.52 22.52,34.62 22.52,36.75 22.47,36.89 22.32,36.95 21.48,36.95 21.33,36.89 21.27,36.75 21.27,35.12 21.25,35.05 21.18,35.02 20.18,35.02 20.07,35.07 20.02,35.17 20.02,37.07 20.03,37.1 20.05,37.14 20.41,37.5 20.45,37.52 20.48,37.52 23.41,37.52 23.45,37.52 23.48,37.5 23.61,37.37 23.65,37.26 23.65,35.9 23.62,35.83 23.55,35.8 23.2,35.8 23.06,35.74 23,35.6 23,34.9 23.06,34.76 23.2,34.7 23.55,34.7 23.62,34.67 23.65,34.6 23.65,34.58 23.62,34.5 23.55,34.48
VEE_B on BOTTOM: 30.24,16.6 30.2,16.61 30.17,16.63 29.89,16.91 29.85,17.01 29.85,20.7 29.88,20.77 29.95,20.8 31.84,20.8 31.94,20.76 32.36,20.34 32.46,20.3 36.34,20.3 36.44,20.26 37.37,19.33 37.39,19.3 37.4,19.26 37.4,16.75 37.36,16.64 37.25,16.6
VEE_B on BOTTOM: 18.35,4.25 18.24,4.29 18.2,4.4 18.2,6.2 18.24,6.31 18.35,6.35 20.1,6.35 20.21,6.31 20.25,6.2 20.25,4.4 20.21,4.29 20.1,4.25
VEE_B on BOTTOM: 26.11,50.5 26.04,50.53 26.01,50.6 26.01,53.2 26.02,53.24 26.04,53.27 26.24,53.47 26.27,53.49 26.31,53.5 26.68,53.5 26.78,53.46 26.82,53.35 26.82,52.55 26.88,52.41 27.02,52.35 28.45,52.35 28.56,52.31 28.6,52.2 28.6,51.45 28.57,51.38 28.5,51.35 27.85,51.35 27.71,51.29 27.65,51.15 27.65,50.6 27.62,50.53 27.55,50.5
VEE_B on BOTTOM: outline of 170 points within 12.2,19.9 21.05,32.85 ; 3 cut-outs
VEE_B on BOTTOM: 23.05,22.35 22.98,22.38 22.95,22.45 22.95,23.2 22.89,23.34 22.75,23.4 21.85,23.4 21.74,23.44 21.7,23.55 21.7,24.3 21.73,24.37 21.8,24.4 22.45,24.4 22.59,24.46 22.65,24.6 22.65,25.15 22.68,25.22 22.75,25.25 23.63,25.25 23.73,25.21 23.78,25.1 23.78,22.5 23.73,22.39 23.63,22.35
VEE_B on BOTTOM: 25.4,30.45 25.34,30.59 25.2,30.65 24.05,30.65 23.98,30.68 23.95,30.75 23.95,31.05 23.93,31.15 23.88,31.23 22.88,32.22 22.86,32.26 22.85,32.3 22.85,32.9 22.89,33.01 23,33.05 25.29,33.05 25.33,33.04 25.36,33.02 26.42,31.96 26.44,31.93 26.45,31.89 26.45,31 26.41,30.89 26.3,30.85 25.85,30.85 25.71,30.79 25.65,30.65 25.65,30 25.61,29.89 25.5,29.85 25.43,29.88 25.4,29.95
VEE_B on BOTTOM: 36.25,22.2 36.18,22.23 36.15,22.3 36.15,24.4 36.18,24.47 36.25,24.5 37,24.5 37.07,24.47 37.1,24.4 37.1,22.3 37.07,22.23 37,22.2
VEE_B on CONDUCTIVE3: 22.95,22.8 23.75,22.8
VEE_B on CONDUCTIVE3: outline of 332 points within 17.1,2.2 43,65 ; 20 cut-outs
SIG00131 on TOP: 72.7,44.25 72.59,44.29 72.55,44.4 72.55,49.85 72.59,49.96 72.7,50 74.05,50 74.16,49.96 74.2,49.85 74.2,49.35 75.26,48.29 75.36,48.25 82.65,48.25 82.72,48.22 82.75,48.15 82.75,44.51 82.74,44.46 82.58,44.28 82.55,44.26 82.51,44.25
SIG00133 on TOP: 73.65,54.15 73.54,54.19 73.5,54.3 73.5,59.16 73.51,59.2 73.53,59.23 73.62,59.32 73.65,59.34 73.69,59.35 82.16,59.35 82.2,59.34 82.23,59.32 82.77,58.78 82.79,58.75 82.8,58.71 82.8,55.45 82.77,55.38 82.7,55.35 75,55.35 74.14,54.49 74.1,54.39 74.1,54.3 74.06,54.19 73.95,54.15
SIG00135 on BOTTOM: 78.5,57.65 78.39,57.69 78.35,57.8 78.35,60.4 78.39,60.51 78.5,60.55 81.8,60.55 81.91,60.51 81.95,60.4 81.95,57.8 81.91,57.69 81.8,57.65
SIG00136 on BOTTOM: 78.5,54.6 78.39,54.64 78.35,54.75 78.35,56.5 78.39,56.61 78.5,56.65 81.8,56.65 81.91,56.61 81.95,56.5 81.95,54.75 81.91,54.64 81.8,54.6
SIG00154 on TOP: 15.49,6.95 15.45,6.96 15.42,6.98 15.23,7.17 15.21,7.2 15.2,7.24 15.2,10.85 15.23,10.92 15.3,10.95 23,10.95 23.86,11.81 23.9,11.91 23.9,12 23.94,12.11 24.05,12.15 24.35,12.15 24.46,12.11 24.5,12 24.5,7.14 24.49,7.1 24.47,7.07 24.38,6.98 24.35,6.96 24.31,6.95
SIG00157 on TOP: 23.95,16.3 23.84,16.34 23.8,16.45 23.8,16.95 22.74,18.01 22.64,18.05 15.35,18.05 15.28,18.08 15.25,18.15 15.25,21.79 15.26,21.84 15.42,22.02 15.45,22.04 15.49,22.05 25.3,22.05 25.41,22.01 25.45,21.9 25.45,16.45 25.41,16.34 25.3,16.3
SIG00159 on BOTTOM: 18.35,6.65 18.24,6.69 18.2,6.8 18.2,9.4 18.24,9.51 18.35,9.55 21.65,9.55 21.76,9.51 21.8,9.4 21.8,6.8 21.76,6.69 21.65,6.65
SIG00160 on BOTTOM: 18.35,10.55 18.24,10.59 18.2,10.7 18.2,12.45 18.24,12.56 18.35,12.6 21.65,12.6 21.76,12.56 21.8,12.45 21.8,10.7 21.76,10.59 21.65,10.55
VE_A on TOP: outline of 91 points within 54,48.2 98,66 ; 1 cut-out
VE_A on TOP: 68.25,42.65 68.18,42.68 68.15,42.75 68.15,45.9 68.18,45.97 68.25,46 68.85,46 68.92,45.97 68.95,45.9 68.95,44.65 68.99,44.54 69.1,44.5 69.55,44.5 69.62,44.47 69.65,44.4 69.65,42.75 69.62,42.68 69.55,42.65
VE_A on TOP: 66.25,53 66.14,53.04 66.1,53.15 66.1,58.71 66.11,58.75 66.13,58.78 66.47,59.12 66.5,59.14 66.54,59.15 68.8,59.15 68.91,59.11 68.95,59 68.95,53.15 68.91,53.04 68.8,53
VE_A on TOP: outline of 83 points within 54,31.19 72.75,44.2 ; 7 cut-outs
VE_A on TOP: 63,21.9 64.07,21.31 64.01,22.53 63.97,22.57 63.95,22.62 63.95,23.15 63.99,23.25 64.1,23.3 64.95,23.3 65.02,23.27 65.05,23.2 65.05,21.24 65.01,21.13 64.48,20.6 64.45,20.58 64.41,20.57 62.89,20.58 62.81,20.61 62.79,20.7 62.46,21.24 61.91,20.91 61.84,20.64 61.81,20.59 61.75,20.57 61.35,20.57 61.26,20.56 61.19,20.51 60.98,20.3 60.92,20.27 60.85,20.28 60.84,20.29 60.19,20.42 59.73,19.95 59.69,19.89 59.63,19.88 57.61,19.88 57.55,19.89 57.54,19.91 56.63,20.3 55.74,19.88 55.7,19.86 55.67,19.85 55.52,19.85 55.45,19.88 55.42,19.95 55.42,20.87 55.43,20.9 55.45,20.94 56.63,22.12 56.73,22.18 56.76,22.2 56.79,22.2 59.1,22.2 59.25,22.24 59.36,22.35 59.37,22.37 59.39,22.38 59.42,22.4 59.45,22.4 62.74,22.4 62.84,22.36 62.97,22.23 62.99,22.2 63,22.16 ; 1 cut-out
VE_A on TOP: outline of 99 points within 58.45,12.75 71.1,20.95
VE_A on BOTTOM: 88.49,53.9 88.45,53.91 88.42,53.93 87.14,55.21 87.1,55.31 87.1,61.65 87.03,61.89 86.84,62.06 86.77,62.08 86.73,62.09 86.69,62.1 86.65,62.1 85.15,62.1 84.83,61.97 84.7,61.65 84.7,57.55 84.66,57.44 84.55,57.4 83.6,57.4 83.49,57.44 83.45,57.55 83.45,61.75 83.36,61.96 83.15,62.05 75.51,62.05 75.47,62.06 75.44,62.08 74.66,62.86 74.59,62.91 74.5,62.92 54.54,62.92 54.43,62.97 54.03,63.37 54.01,63.4 54,63.44 54,65.9 54.03,65.97 54.1,66 93.65,66 93.73,65.97 93.75,65.9 94.01,64.43 94.85,63.2 94.85,63.2 96.26,62.39 97.88,62.31 97.96,62.29 98,62.21 98,49.15 97.97,49.08 97.9,49.05 95.6,49.05 95.53,49.08 95.5,49.15 95.5,51.59 95.44,51.81 95.37,51.91 93.49,53.78 93.36,53.87 93.21,53.9 ; 1 cut-out
VE_A on CONDUCTIVE2: 98,43.25 97.96,43.14 97.85,43.1 97.54,43.1 97.5,43.1 97.47,43.12 96.47,43.57 95.45,43.95 79.59,39.04 78.9,22.45 78.9,22.45 80.17,20.76 81.67,19.28 81.71,19.23 81.73,19.16 81.73,16.09 81.71,16.02 81.67,15.97 77.4,9.73 76.88,2.18 76.88,2.18 76.85,2.05 76.73,2 50.15,2 50.04,2.04 50,2.15 50,65.85 50.04,65.96 50.15,66 93.6,66 93.71,65.96 93.75,65.85 93.75,65.85 93.91,64.71 94.42,63.69 95.93,62.51 97.83,62.3 97.95,62.26 98,62.15 ; 91 cut-outs
VE_B on TOP: outline of 117 points within 2,2 29.55,40.9 ; 1 cut-out
VE_B on TOP: 29.2,7.15 29.09,7.19 29.05,7.3 29.05,13.15 29.09,13.26 29.2,13.3 31.2,13.3 31.31,13.26 31.35,13.15 31.35,7.3 31.31,7.19 31.2,7.15
VE_B on TOP: outline of 163 points within 28.15,25.95 40.52,42.5 ; 4 cut-outs
VE_B on TOP: outline of 81 points within 18.5,19.45 32.85,28.65 ; 2 cut-outs
VE_B on BOTTOM: outline of 90 points within 2,1.6 29.3,42.75
VGATE_A on TOP: 88.01,45.4 87.91,45.44 84.6,48.75 75.4,48.75 75.29,48.79 75.25,48.9 75.25,54.7 75.29,54.81 75.4,54.85 90.39,54.85 91,54.8 91.61,54.85 93.49,54.85 93.59,54.81 94.87,53.53 94.89,53.5 94.9,53.46 94.9,47.16 94.86,47.06 93.23,45.43 93.2,45.41 93.16,45.4
VGATE_A on BOTTOM: 78.19,45.5 78.15,45.51 78.12,45.53 77.34,46.31 77.24,46.35 73.75,46.35 73.68,46.38 73.65,46.45 73.65,49.59 73.69,49.69 75.41,51.41 75.51,51.45 77.19,51.45 77.29,51.49 78.16,52.36 78.2,52.46 78.2,53.44 78.24,53.54 78.27,53.57 78.3,53.59 78.34,53.6 93.21,53.6 93.25,53.59 93.28,53.57 95.16,51.69 95.2,51.59 95.2,46.76 95.16,46.66 94.03,45.53 94,45.51 93.96,45.5
VGATE_A on CONDUCTIVE3: 80.77,50.9 80.71,50.91 80.66,50.94 80.6,51.01 80.57,51.05 80.56,51.11 80.56,51.91 80.51,52.01 73.54,58.98 73.52,59.01 73.51,59.04 73.5,59.09 73.5,61.45 73.54,61.56 73.65,61.6 77.19,61.6 77.25,61.59 77.29,61.56 82.4,56.45 82.42,56.42 82.44,56.39 82.44,56.34 82.44,52.41 82.44,52.19 82.44,51.25 82.44,51.22 82.3,50.99 82.05,50.9 ; 1 cut-out
VGATE_B on TOP: 7.16,10.95 7.06,10.99 5.48,12.57 5.46,12.6 5.45,12.64 5.45,16.61 5.46,16.65 5.48,16.68 6.71,17.91 6.81,17.95 10.24,17.95 10.34,17.91 10.66,17.59 10.77,17.54 22.6,17.54 22.71,17.5 22.75,17.39 22.75,11.6 22.71,11.49 22.6,11.45 11.06,11.45 10.96,11.41 10.54,10.99 10.44,10.95
VGATE_B on BOTTOM: 5.76,11.1 5.66,11.14 4.88,11.92 4.86,11.95 4.85,11.99 4.85,16.96 4.86,17 4.88,17.03 5.71,17.86 5.81,17.9 16.34,17.9 16.44,17.94 17.17,18.67 17.2,18.69 17.24,18.7 19.44,18.7 19.54,18.74 20.51,19.71 20.61,19.75 23,19.75 23.11,19.71 23.15,19.6 23.15,13.75 23.11,13.64 23,13.6 18.1,13.6 17.99,13.56 17.95,13.45 17.95,11.2 17.92,11.13 17.85,11.1
VGD_A on TOP: 57.8,54.7 57.73,54.73 57.7,54.8 57.7,58.8 57.73,58.87 57.8,58.9 58.55,58.9 58.66,58.94 58.7,59.05 58.66,59.16 58.55,59.2 58.1,59.2 58.03,59.23 58,59.3 58,60.75 58.03,60.82 58.1,60.85 60.05,60.85 60.12,60.82 60.15,60.75 60.15,54.85 60.11,54.74 60,54.7
VGD_A on BOTTOM: 58.5,54.7 58.39,54.74 58.35,54.85 58.35,56.35 58.39,56.46 58.5,56.5 60.84,56.5 60.94,56.46 61.66,55.74 61.76,55.7 62.65,55.7 62.72,55.67 62.75,55.6 62.75,54.85 62.71,54.74 62.6,54.7
VGD_B on BOTTOM: 34.1,11.6 33.99,11.64 33.95,11.75 33.95,13.59 33.91,13.69 33.45,14.15 33.42,14.21 33.44,14.27 33.22,14.92 32.61,14.61 32.54,14.32 32.53,14.3 32.51,14.28 32.46,14.23 32.43,14.21 32.39,14.2 29.75,14.2 29.64,14.24 29.6,14.35 29.6,15.95 29.64,16.06 29.75,16.1 34.49,16.1 34.59,16.06 36.62,14.03 36.64,14 36.65,13.96 36.65,11.75 36.61,11.64 36.5,11.6
VL_A on TOP: 54.1,22.45 54.03,22.48 54,22.55 54,25.86 54.01,25.9 54.03,25.93 54.33,26.23 54.37,26.26 54.41,26.26 54.8,26.26 54.82,26.26 55.29,26.34 55.6,26.69 55.62,26.72 55.65,26.74 55.69,26.75 59.1,26.75 59.21,26.71 59.25,26.6 59.25,24.84 59.24,24.8 59.22,24.77 59.13,24.68 59.1,24.66 59.06,24.65 58.46,24.65 58.39,24.68 58.36,24.75 58.36,25.44 58.3,25.58 58.16,25.64 57.24,25.64 57.1,25.58 57.04,25.44 57.04,24.07 57.03,24.05 57,23.94 56.99,23.86 56.99,23.48 56.98,23.44 56.96,23.41 56.73,23.18 56.7,23.16 56.66,23.15 56.36,22.99 56.25,22.67 56.26,22.55 56.23,22.48 56.16,22.45
VL_A on BOTTOM: 66.08,44.8 66,44.84 65.99,44.93 66,44.97 66,45 66,46.31 66.01,46.35 66.03,46.38 66.32,46.67 66.36,46.69 66.42,46.69 66.65,46.65 66.88,46.69 67.04,46.74 67.07,46.75 68.25,46.75 68.33,46.76 68.43,46.8 68.46,46.8 69.7,46.8 69.84,46.86 69.9,47 69.9,47.7 69.94,47.81 70.05,47.85 70.8,47.85 71.14,47.94 71.4,48.19 71.55,48.45 71.57,48.47 72.71,49.61 72.81,49.65 73.2,49.65 73.31,49.61 73.35,49.5 73.35,46.71 73.31,46.61 72.13,45.43 72.1,45.41 72.06,45.4 68.21,45.4 68.11,45.36 67.58,44.83 67.55,44.81 67.51,44.8
VL_A on CONDUCTIVE3: outline of 147 points within 50,3.65 69.19,51.3 ; 12 cut-outs
VL_B on BOTTOM: 21.05,26.65 20.94,26.69 20.9,26.8 20.9,28.85 20.94,28.96 21.05,29 22.24,29 22.34,29.04 22.62,29.32 22.65,29.34 22.69,29.35 25.5,29.35 25.61,29.31 25.65,29.2 25.65,28.55 25.71,28.41 25.85,28.35 26.65,28.35 26.72,28.32 26.75,28.25 26.75,26.8 26.71,26.69 26.6,26.65 24.27,26.65 24.2,26.68 24.18,26.75 24.18,27.4 24.22,27.51 24.32,27.55 25.2,27.55 25.34,27.61 25.4,27.75 25.4,28.55 25.34,28.69 25.2,28.75 23.5,28.75 23.36,28.69 23.3,28.55 23.3,27.76 23.26,27.66 22.28,26.68 22.25,26.66 22.21,26.65
VL_B on CONDUCTIVE3: outline of 331 points within 11.95,19.85 36.4,55.7 ; 6 cut-outs
N03856 on TOP: 54,30.46 54.03,30.53 54.1,30.56 58.98,30.56 59.09,30.52 59.13,30.41 59.13,30.39 59.64,29.78 60.23,30.32 60.23,30.54 60.27,30.64 60.31,30.68 60.34,30.7 60.38,30.71 63.3,30.71 63.8,31.21 63.8,32.3 63.7,32.4 63.44,32.4 63.4,32.41 63.37,32.43 62.98,32.82 62.96,32.85 62.95,32.89 62.95,34.3 62.99,34.41 63.1,34.45 64.95,34.45 65.06,34.41 65.1,34.3 65.1,32.95 65.17,32.88 65.19,32.85 65.2,32.81 65.2,28.89 65.19,28.85 65.17,28.82 64.33,27.98 64.3,27.96 64.26,27.95 61.95,27.95 61.66,27.85 61.47,27.52 61.41,27.5 54.1,27.5 54.03,27.53 54,27.6 ; 2 cut-outs
N502328 on TOP: 31.69,28.36 31.67,28.38 31.66,28.41 31.38,28.79 30.91,28.81 30.87,28.8 26.8,28.8 26.73,28.83 26.7,28.9 26.7,31.45 26.74,31.56 26.85,31.6 32.5,31.6 32.61,31.56 33.66,30.5 38.61,30.5 38.65,30.49 38.68,30.47 38.87,30.28 38.89,30.25 38.9,30.21 38.9,28.04 38.89,28 38.87,27.97 38.58,27.68 38.55,27.66 38.51,27.65 32.44,27.65 32.4,27.66 32.37,27.68 ; 3 cut-outs
N855623 on BOTTOM: 58.98,13.58 59.01,13.64 59.08,13.64 59.32,13.52 59.36,13.45 59.31,13.39 59.08,13.28 59.01,13.28 58.98,13.34

Small or netless copper shapes (teardrops, artwork), in the pictures only: 122 on TOP, 197 on BOTTOM, 1 on CONDUCTIVE2

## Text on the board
Ref Des/Silkscreen Bottom: P6 | P7 | C81 | C83 | P8 | R77 | C88 | IC29 | R82 | R84 | C80 | IC28 | P5 | C110 | C103 | Q13 | IC31 | R79 | C85 | Q11 | Q12 | D25 | C147 | R124 | IC32 | C149 | Q28 | IC41 | C112 | R151 | IC38 | C105 | Q29 | R83 | C86 | R152 | R184 | R163 | R155 | R157 | R150 | R161 | C140 | R81 | R76 | R188 | R178 | R175 | R176 | C116 | C121 | R160 | R153 | IC51 | R127 | R128 | IC53 | C124 | Q21 | D42 | C24 | IC7 | IC36 | R137 | R125 | R130 | R134 | C96 | R136 | IC34 | R126 | IC37 | C100 | C93 | C94 | R66 | R71 | C74 | C70 | Q22 | C73 | R68 | C71 | IC22 | C72 | R69 | C76 | R72 | Q7 | R74 | IC26 | Q8 | Q9 | R104 | D24 | C122 | C98 | C91 | P1 | P4 | P3 | P2 | C142 | IC54 | IC60 | C134 | IC61 | IC58 | C137 | C143 | IC59 | IC56 | C138 | C136 | D41 | D40 | Q14 | C82 | R80 | IC33 | R75 | C87 | R116 | R122 | R162 | Q20 | R115 | R121 | C148 | R78 | R114 | R120 | IC64 | C111 | C79 | R119 | R107 | R183 | C106 | Q30 | Q31 | R159 | R154 | R164 | R168 | IC30 | C141 | C84 | C118 | IC11 | R133 | D43 | R131 | IC47 | IC55 | C127 | C133 | C28 | C113 | IC43 | C117 | IC46 | R187 | Q24 | R135 | Q23 | C128 | R138 | R179 | Q25 | R98 | C99 | Q10 | R70 | R67 | IC24 | R177 | C77 | C78 | C75 | IC27 | R73 | C123 | C69 | IC23 | IC49 | TP39 | IC25 | C115 | IC44 | IC48 | C119 | R65 | IC45 | C114 | R100 | R94 | IC42 | Q17 | R101 | R95 | R102 | R96 | D33 | D32
Ref Des/Silkscreen Top: P6 | P7 | D37 | P5 | P8 | IC21 | D36 | C66 | TP19 | TP16 | D35 | TP47 | R54 | TP48 | R48 | R49 | R169 | Q19 | Q18 | R158 | TP42 | R181 | R173 | D34 | R156 | R171 | C109 | R123 | R110 | C156 | C157 | C102 | C152 | IC57 | IC65 | C59 | R182 | C135 | C108 | C57 | IC40 | D39 | IC19 | IC39 | C139 | R165 | Q27 | R56 | R51 | TP44 | TP14 | TP43 | R142 | R140 | R34 | R30 | R35 | TP45 | C126 | C155 | C39 | R146 | IC14 | IC35 | R87 | IC17 | R33 | R143 | R144 | TP41 | C154 | R103 | C153 | C90 | R90 | C97 | Q15 | Q16 | D26 | TP11 | TP46 | R85 | R86 | D27 | D28 | P2 | P1 | P3 | P4 | D29 | C104 | R109 | TP40 | R118 | R108 | C58 | R117 | R111 | C56 | C67 | IC18 | R113 | R112 | C146 | IC62 | C144 | R106 | C54 | R105 | TP17 | C160 | C107 | TP37 | TP35 | R52 | R55 | C158 | D38 | C101 | CN3 | C151 | R180 | R167 | R172 | R129 | C120 | C131 | R132 | R147 | CN2 | IC15 | C48 | R31 | TP30 | C159 | TP12 | C40 | TP32 | R149 | C89 | IC50 | C35 | C47 | C95 | D30 | R28 | R139 | R27 | C37 | D31 | C129 | C38 | C132 | R92 | R93 | R91 | R97 | R88 | R99 | R89 | C92
SYMBOL-1-TOP: 1 | 9 | 10 | 2 | RD258-2
SYMBOL-1-BOTTOM: 1 | 9 | 10 | 2
